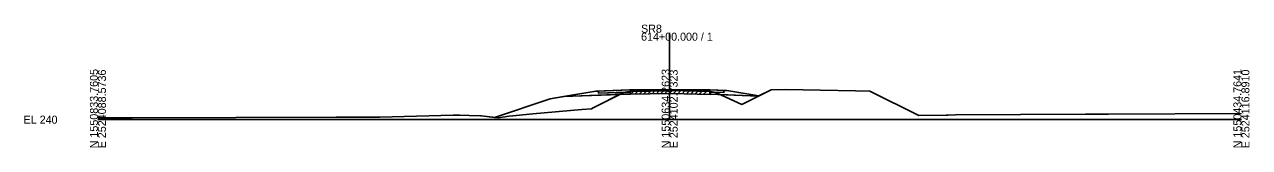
# Model space of a CAD drawing. Extents: x -26 to 2803, y -10 to 19537.
# Drawn here: x -25.7 to 402.8, y 18990.3 to 19033.2 of the extents above; entities that cross this region are included whole.
import ezdxf

# ---------------------------------------------------------------- set-up
doc = ezdxf.new("R2010")
doc.units = 0
for name, color, linetype in [('1', 7, 'Continuous'), ('Draft_XS_Grid', 7, 'Continuous'), ('Draft_XS_Text', 7, 'Continuous'), ('DTM_P_SUBGRADE_1', 7, 'Continuous'), ('DTM_X_GROUND', 7, 'Continuous'), ('SLOPE_STAKES_FILL', 7, 'Continuous'), ('XS_P_ASPHALT', 7, 'Continuous'), ('XS_P_SHOULDER', 7, 'Continuous')]:
    doc.layers.add(name, color=color, linetype=linetype)

msp = doc.modelspace()

# ---------------------------------------------------------------- linework, layer by layer
at = {"layer": '1'}
for p, q in [((200, 19000), (200, 19030.35)), ((0, 19000), (200, 19000)), ((200, 19000), (400, 19000))]:
    msp.add_line(p, q, dxfattribs=at)
at = {"layer": 'Draft_XS_Grid'}
for p, q in [((186.35, 19008.85), (187.37, 19009.87)), ((186.35, 19008.85), (186.35, 19009.85)), ((187.85, 19008.88), (188.87, 19009.9)), ((189.35, 19008.91), (190.37, 19009.93)), ((190.85, 19008.94), (191.87, 19009.96)), ((192.35, 19008.96), (193.37, 19009.98)), ((193.85, 19008.99), (194.87, 19010.01)), ((195.35, 19009.02), (196.37, 19010.04)), ((196.85, 19009.05), (197.87, 19010.07)), ((198.35, 19009.08), (199.37, 19010.1)), ((199.85, 19009.1), (200.85, 19010.11)), ((201.35, 19009.1), (202.33, 19010.08)), ((202.85, 19009.06), (203.83, 19010.04)), ((204.35, 19009.03), (205.33, 19010.01)), ((205.85, 19009), (206.83, 19009.98)), ((207.35, 19008.97), (208.33, 19009.95)), ((208.85, 19008.94), (209.83, 19009.92)), ((210.35, 19008.91), (211.33, 19009.89)), ((211.85, 19008.87), (212.83, 19009.85)), ((214.29, 19009.82), (214.29, 19008.82)), ((186.35, 19008.85), (200, 19009.11)), ((200, 19009.11), (200.46, 19009.12)), ((200.46, 19009.12), (214.29, 19008.82))]:
    msp.add_line(p, q, dxfattribs=at)
at = {"layer": 'Draft_XS_Text'}
for p, q in [((225.25, 19005.31), (235.53, 19010.37)), ((235.53, 19010.37), (240.61, 19010.57)), ((240.61, 19010.57), (252.8, 19010.33)), ((252.8, 19010.33), (264.98, 19010.09)), ((264.98, 19010.09), (270.06, 19009.89)), ((270.06, 19009.89), (287.15, 19001.48))]:
    msp.add_line(p, q, dxfattribs=at)
for points in [[(0, 19000.61), (11.66, 19000.64), (11.97, 19000.64), (48.22, 19000.7), (83.31, 19000.83), (83.63, 19000.83), (96.59, 19000.88), (98.63, 19000.89), (124.26, 19001.52), (126.55, 19001.57), (129.82, 19001.47), (133.77, 19001.34), (134.2, 19001.33), (140.14, 19000.64), (143.79, 19001.17), (145.08, 19001.36), (152.09, 19001.98), (169.22, 19003.5), (172.71, 19003.81), (173.25, 19004.09), (183.88, 19009.5), (185.2, 19009.69), (186.35, 19009.85), (200, 19010.11), (200.46, 19010.12), (214.29, 19009.82), (216.27, 19009.38), (216.89, 19009.1), (225.25, 19005.31)], [(287.15, 19001.48), (296.72, 19001.61), (297.41, 19001.62), (299.99, 19001.72), (345.47, 19001.87), (346.17, 19001.88), (347.8, 19001.89), (348.21, 19001.89), (348.87, 19001.89), (350.14, 19001.9), (353.55, 19001.92), (400, 19002.17)]]:
    msp.add_lwpolyline(points, dxfattribs=at)
at = {"layer": 'DTM_P_SUBGRADE_1'}
for p, q in [((184, 19008.88), (162.89, 19008.04)), ((186.35, 19008.88), (184, 19008.88)), ((186.35, 19009.65), (186.35, 19008.88)), ((214, 19009.63), (214, 19008.88)), ((214, 19008.88), (231.11, 19008.2)), ((231.11, 19008.2), (231.25, 19008.27))]:
    msp.add_line(p, q, dxfattribs=at)
at = {"layer": 'DTM_X_GROUND'}
for p, q in [((174.13, 19009.91), (158.18, 19007.26)), ((186, 19010.38), (174.13, 19009.91)), ((200, 19010.38), (186, 19010.38)), ((200, 19010.38), (214, 19010.38)), ((214, 19010.38), (220, 19010.14)), ((220, 19010.14), (231.25, 19008.27)), ((158.18, 19007.26), (138.77, 19000.8))]:
    msp.add_line(p, q, dxfattribs=at)
at = {"layer": 'SLOPE_STAKES_FILL'}
for p, q in [((158.18, 19007.26), (174.13, 19009.91)), ((174.13, 19009.91), (186, 19010.38)), ((186, 19010.38), (200, 19010.38)), ((200, 19010.38), (214, 19010.38)), ((214, 19010.38), (220, 19010.14)), ((220, 19010.14), (231.25, 19008.27)), ((231.25, 19008.27), (235.53, 19010.37)), ((235.53, 19010.37), (240.61, 19010.57)), ((240.61, 19010.57), (252.8, 19010.33)), ((252.8, 19010.33), (264.98, 19010.09)), ((264.98, 19010.09), (270.06, 19009.89)), ((270.06, 19009.89), (287.15, 19001.48)), ((138.77, 19000.8), (158.18, 19007.26))]:
    msp.add_line(p, q, dxfattribs=at)
for points in [[(0, 19000.61), (11.66, 19000.64), (11.97, 19000.64), (48.22, 19000.7), (83.31, 19000.83), (83.63, 19000.83), (96.59, 19000.88), (98.63, 19000.89), (124.26, 19001.52), (126.55, 19001.57), (129.82, 19001.47), (133.77, 19001.34), (134.2, 19001.33), (138.77, 19000.8)], [(287.15, 19001.48), (296.72, 19001.61), (297.41, 19001.62), (299.99, 19001.72), (345.47, 19001.87), (346.17, 19001.88), (347.8, 19001.89), (348.21, 19001.89), (348.87, 19001.89), (350.14, 19001.9), (353.55, 19001.92), (400, 19002.17)]]:
    msp.add_lwpolyline(points, dxfattribs=at)
at = {"layer": 'XS_P_ASPHALT'}
for p, q in [((175.13, 19009.2), (175.13, 19009.95)), ((186.35, 19009.65), (186.35, 19010.38)), ((214, 19009.63), (214, 19010.38)), ((218.97, 19009.43), (218.97, 19010.18)), ((186.35, 19009.65), (175.13, 19009.2)), ((214, 19009.63), (218.97, 19009.43))]:
    msp.add_line(p, q, dxfattribs=at)
at = {"layer": 'XS_P_SHOULDER'}
for points in [[(175.13, 19009.2), (175.13, 19009.95), (174.13, 19009.91), (162.89, 19008.04), (182.56, 19008.83), (183.88, 19009.5), (184.38, 19009.57)], [(175.13, 19009.2), (175.13, 19009.95), (186, 19010.38), (186.35, 19010.38), (186.35, 19009.85), (185.2, 19009.69), (184.38, 19009.57)], [(184.38, 19009.57), (185.2, 19009.69), (186.35, 19009.85), (186.35, 19009.65)], [(200, 19010.38), (186.35, 19010.38), (186.35, 19009.85), (200, 19010.11), (200.46, 19010.12), (214, 19009.83), (214, 19010.38)], [(214, 19010.38), (218.97, 19010.18), (218.97, 19009.43), (215.4, 19009.58), (214.29, 19009.82), (214, 19009.83)], [(214.29, 19009.82), (214.29, 19009.62), (214, 19009.63), (214, 19009.83)], [(214.29, 19009.82), (215.4, 19009.58), (214.29, 19009.62)], [(218.97, 19010.18), (220, 19010.14), (231.25, 19008.27), (231.11, 19008.2), (217.7, 19008.73), (216.89, 19009.1), (216.27, 19009.38), (215.4, 19009.58), (218.97, 19009.43)], [(143.79, 19001.17), (145.08, 19001.36), (152.09, 19001.98), (169.22, 19003.5), (172.71, 19003.81), (173.25, 19004.09), (182.56, 19008.83), (162.89, 19008.04), (158.18, 19007.26), (138.77, 19000.8), (140.14, 19000.64)], [(186.35, 19008.88), (184, 19008.88), (182.56, 19008.83), (183.88, 19009.5), (184.38, 19009.57), (186.35, 19009.65)], [(214, 19008.88), (214.29, 19008.87), (214.29, 19009.62), (214, 19009.63)], [(216.89, 19009.1), (217.7, 19008.73), (214.29, 19008.87), (214.29, 19009.62), (215.4, 19009.58), (216.27, 19009.38)], [(217.7, 19008.73), (225.25, 19005.31), (231.11, 19008.2)]]:
    msp.add_lwpolyline(points, close=True, dxfattribs=at)

# ---------------------------------------------------------------- texts
at = {"layer": '1'}
for s, p in [('SR8', (190, 19030.35)), ('614+00.000 / 1', (190, 19027.55)), ('EL 240', (-26, 18998.6))]:
    msp.add_text(s, height=2.8, dxfattribs=at).set_placement(p)
for s, p in [('N 1550833.7605', (0, 18990)), ('E 2524088.5736', (2.8, 18990)), ('N 1550634.2623', (200, 18990)), ('E 2524102.7323', (202.8, 18990)), ('N 1550434.7641', (400, 18990)), ('E 2524116.8910', (402.8, 18990))]:
    msp.add_text(s, height=2.8, rotation=90, dxfattribs=at).set_placement(p)

doc.saveas('drawing.dxf')
